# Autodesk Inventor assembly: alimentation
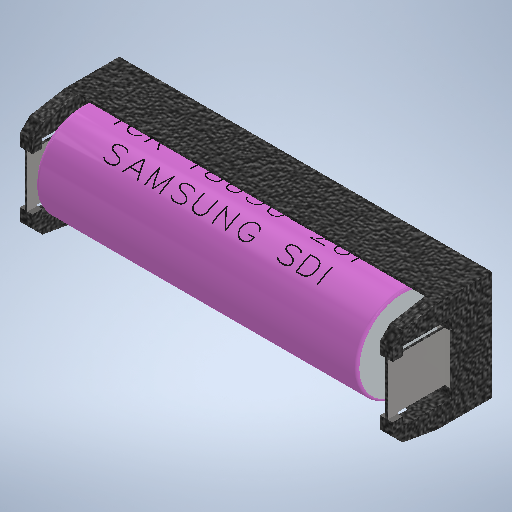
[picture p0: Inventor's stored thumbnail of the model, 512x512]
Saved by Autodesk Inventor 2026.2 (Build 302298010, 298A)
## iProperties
Created: 2026-09
Part Number: alimentation
Document SubType Name: Assembly
Designer: mel
Author: mel
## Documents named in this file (3)
- D:\travail\année 2026-2027\1 sti2d IT\poubelle à verre\alimentation.iam
- D:\travail\année 2026-2027\1 sti2d IT\poubelle à verre\porte pile.ipt
- D:\travail\année 2026-2027\1 sti2d IT\poubelle à verre\Samsung icr18650\Samsung icr18650\Samsung icr18650.ipt
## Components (2 placed, 2 different names)
1. porte pile:1 — Logement:1
2. Samsung icr18650:1 — Logement:1
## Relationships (1: Insert 1)
- Logement:1 [Insert]: porte pile:1 ↔ Samsung icr18650:1
